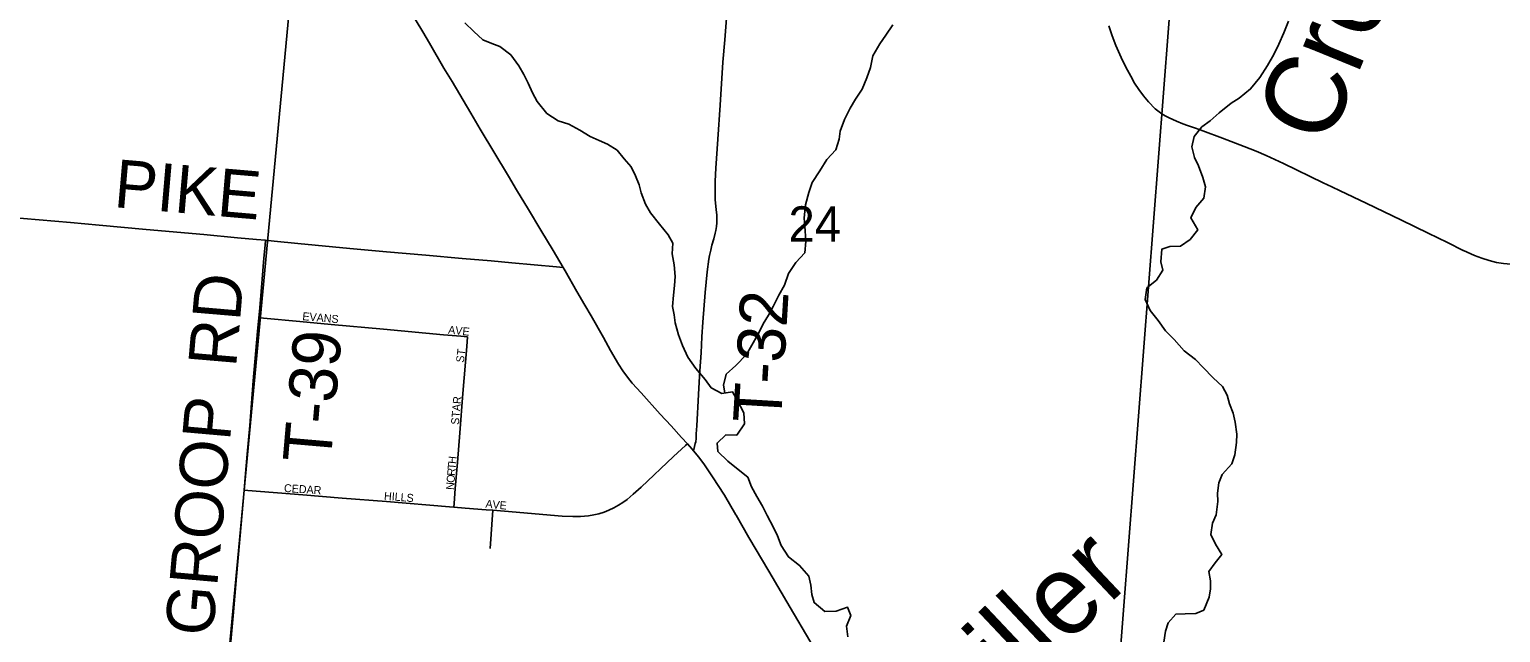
# Model space of a CAD drawing. Extents: x 1410790 to 1770854, y 566777 to 831614.
# Drawn here: x 1576682 to 1585877, y 711218 to 714986 of the extents above; entities that cross this region are included whole.
import ezdxf

# ---------------------------------------------------------------- set-up
doc = ezdxf.new("R2010")
doc.units = 0
for name, color, linetype in [('GM_X_County_Road', 7, 'Continuous'), ('GM_X_County_Road_Text', 7, 'Continuous'), ('GM_X_Minor_River', 7, 'Continuous'), ('GM_X_Minor_River_Text', 7, 'Continuous'), ('GM_X_Section', 7, 'Continuous'), ('GM_X_Section_Text', 7, 'Continuous'), ('GM_X_Township_Road', 7, 'Continuous'), ('GM_X_Township_Road_Text', 7, 'Continuous'), ('GM_X_Township_Subdivision', 7, 'Continuous'), ('GM_X_Township_Subdivision_Text', 7, 'Continuous')]:
    doc.layers.add(name, color=color, linetype=linetype)

msp = doc.modelspace()

# ---------------------------------------------------------------- linework, layer by layer
at = {"layer": 'GM_X_County_Road'}
for points in [[(1580017.1, 713499.7), (1579954.8, 713604.5), (1579879.1, 713731.2), (1579801.5, 713860.8), (1579727.2, 713984.1), (1579676.3, 714068.3), (1579499.3, 714363.7), (1579440.7, 714462.4), (1579323.6, 714659.7), (1579273.3, 714744.1), (1579181.7, 714899.4), (1579140.2, 714970.2), (1579064.6, 715096.8), (1578939.8, 715308.8), (1578831.3, 715492.4), (1578737.5, 715646.4), (1578678.6, 715744.8), (1578619.6, 715843.3), (1578494.3, 716054.8), (1578417.9, 716181.2), (1578356.6, 716278.4), (1578333.9, 716312.2)], [(1572937.4, 714145.1), (1573034.7, 714134.6), (1573198, 714119.1), (1573344.9, 714104.9), (1573590.1, 714084.2), (1573786.2, 714067.5), (1574021.8, 714044.2), (1574325.1, 714017.6), (1574717, 713980.8), (1574864, 713968.2), (1575043.7, 713951.7), (1575419.2, 713916), (1575685.6, 713891.3), (1576121.6, 713852), (1576334, 713832.7), (1576644.5, 713805.3), (1576938.5, 713779), (1577118.3, 713764.1), (1577412.2, 713736.7), (1577771.6, 713704.3), (1577983.2, 713684.6), (1578100.6, 713674)], [(1578100.6, 713674), (1578158.5, 713668.8)], [(1578158.5, 713668.8), (1578212.6, 713663.9), (1578359.1, 713649.3), (1578685.6, 713618.2), (1578914.3, 713597.5), (1579159.3, 713575.4), (1579387.9, 713555.3), (1579567.7, 713539.3), (1579698.3, 713528.2), (1579976, 713503.3), (1580017.1, 713499.7)], [(1580794.3, 712397.1), (1580758.6, 712437.8), (1580692.1, 712510.5), (1580625.1, 712582.4), (1580504.6, 712715), (1580449.6, 712775.8), (1580419.2, 712814.1), (1580390.9, 712853.9), (1580364.3, 712894.9), (1580314.5, 712980.6), (1580269.4, 713060.5), (1580192.1, 713196.7), (1580152.5, 713264.3), (1580103.4, 713349.4), (1580030.2, 713477.6), (1580017.1, 713499.7)], [(1580832.8, 712353), (1580823.6, 712363.8), (1580794.3, 712397.1)], [(1581099.1, 711950.7), (1581096.8, 711954.6), (1581025.4, 712076.1), (1580950.5, 712192.1), (1580901.3, 712266.2), (1580864.9, 712314.8), (1580832.8, 712353)], [(1581826.3, 710707.1), (1581777.2, 710792.2), (1581559.3, 711167.2), (1581435.7, 711374), (1581304.4, 711601.1), (1581179.1, 711812.8), (1581099.1, 711950.7)]]:
    msp.add_lwpolyline(points, dxfattribs=at)
at = {"layer": 'GM_X_Minor_River'}
for points in [[(1583772, 711158.6), (1583782.5, 711226.7), (1583798.9, 711278.7), (1583847.2, 711332.4), (1583905.2, 711336), (1583971.1, 711337.5), (1584021.2, 711359.2), (1584055.8, 711439.1), (1584064.2, 711491.1), (1584064.6, 711541.2), (1584053, 711599.4), (1584093.4, 711653.2), (1584133.7, 711705), (1584094.3, 711771.5), (1584064.8, 711831.8), (1584075.4, 711901.9), (1584099.7, 711953.8), (1584110.4, 712037.9), (1584106.8, 712090), (1584115.2, 712154), (1584137.6, 712206), (1584196.1, 712271.7), (1584216.5, 712327.6), (1584227, 712405.7), (1584227.5, 712457.8), (1584218, 712532), (1584204.5, 712588.2), (1584183, 712646.4), (1584167.4, 712700.7), (1584137.9, 712755), (1584080.4, 712809.5), (1584016.9, 712874.1), (1583969.4, 712924.5), (1583899.9, 712979.1), (1583836.5, 713049.7), (1583783, 713102.2), (1583735.6, 713166.6), (1583686.1, 713231.1), (1583654.7, 713299.4), (1583665.2, 713371.5), (1583725.5, 713419.1), (1583765.9, 713482.9), (1583752.4, 713535.1), (1583758.9, 713613.2), (1583809, 713630.8), (1583876.9, 713632.3), (1583937.2, 713673.9), (1583983.6, 713733.7), (1583940.2, 713808.1), (1583972.7, 713874), (1584023, 713931.7), (1584031.5, 714001.8), (1584016, 714060), (1583988.6, 714134.3), (1583963, 714186.5), (1583947.6, 714252.8), (1583962, 714316.7), (1584010.4, 714376.5), (1584060.6, 714414.1), (1584116.9, 714463.8), (1584193.3, 714525.3), (1584243.5, 714557), (1584313.8, 714614.6), (1584372.3, 714686.2), (1584420.8, 714760), (1584459.3, 714829.8), (1584491.7, 714893.6), (1584522.2, 714963.5), (1584550.7, 715037.4)], [(1581572.1, 711455.9), (1581566.8, 711514.1), (1581553.4, 711570.5), (1581496.1, 711637.4), (1581426.6, 711690.4), (1581381.4, 711763.1), (1581358.1, 711823.6), (1581332.6, 711874.1), (1581293.5, 711948.8), (1581264.1, 712007.3), (1581228.8, 712067.9), (1581195.4, 712128.5), (1581172.1, 712189), (1581112.6, 712237.8), (1581047, 712288.8), (1580985.6, 712349.7), (1580980.3, 712401.9), (1581035.1, 712453.4), (1581103.2, 712450.6), (1581152.2, 712522.3), (1581147.1, 712590.6), (1581106, 712669.3), (1581076.5, 712721.8), (1581010.2, 712712.6), (1580942.5, 712747.4), (1580905, 712800.1), (1580847.7, 712866.9), (1580796.4, 712937.8), (1580763.3, 713012.4), (1580738, 713078.9), (1580718.9, 713153.3), (1580711.5, 713203.6), (1580702.1, 713255.8), (1580707, 713326), (1580713.8, 713386.1), (1580718.5, 713442.2), (1580711.4, 713514.5), (1580700.2, 713584.8), (1580703.1, 713651), (1580673.6, 713703.5), (1580620.3, 713770.3), (1580563, 713841.2), (1580533.6, 713893.7), (1580506.4, 713964.2), (1580493, 714014.5), (1580469.6, 714070.9), (1580442.2, 714127.4), (1580398.7, 714178.1), (1580355.3, 714230.7), (1580295.6, 714269.5), (1580243.7, 714292.2), (1580185.9, 714316.9), (1580122.2, 714355.8), (1580052.5, 714394.7), (1579986.5, 714415.5), (1579916.9, 714460.5), (1579855.7, 714535.4), (1579826.2, 714589.9), (1579798.9, 714650.4), (1579771.5, 714704.9), (1579740.1, 714757.4), (1579690.8, 714826.1), (1579623.2, 714879.1), (1579571.3, 714897.7), (1579515.5, 714920.4), (1579459.9, 714973.2), (1579402.5, 715028)], [(1581029.1, 712715.2), (1581020.9, 712764.6), (1581037.8, 712832.6), (1581096.6, 712886.1), (1581163.7, 712955.5), (1581204.7, 713027.3), (1581243.7, 713095), (1581268.4, 713146.9), (1581301.1, 713200.7), (1581329.9, 713254.5), (1581364.9, 713326.3), (1581401.7, 713388.1), (1581426.7, 713462), (1581471.7, 713529.7), (1581528.6, 713591.2), (1581535.5, 713661.3), (1581530.3, 713727.6), (1581523.3, 713809.9), (1581532.4, 713890), (1581553.4, 713968), (1581574.2, 714029.9), (1581621.2, 714101.6), (1581666.2, 714173.3), (1581723.1, 714232.8), (1581742, 714300.8), (1581748.7, 714350.8), (1581775.6, 714422.7), (1581812.6, 714494.5), (1581845.4, 714550.2), (1581886.3, 714611.9), (1581915.3, 714683.8), (1581938.1, 714747.7), (1581953.1, 714821.8), (1581998.1, 714895.4), (1582034.9, 714949.1), (1582077.8, 715014.8)], [(1581797.4, 711192.3), (1581788.2, 711258.7), (1581815.1, 711324.6), (1581795.7, 711377), (1581723.2, 711351.7), (1581653, 711350.6), (1581587.5, 711405.5), (1581572.1, 711455.9)]]:
    msp.add_lwpolyline(points, dxfattribs=at)
at = {"layer": 'GM_X_Section'}
for points in [[(1573281.6, 716755.8), (1578419.1, 716300.4), (1577923.7, 711041.4), (1572586.3, 711496.1)], [(1578419.1, 716300.4), (1583863.1, 715803.7), (1583457.2, 710550.8), (1577923.7, 711041.4)], [(1589194.8, 715318.7), (1588736.5, 710042.5), (1583457.2, 710550.8), (1583863.1, 715803.7)]]:
    msp.add_lwpolyline(points, close=True, dxfattribs=at)
at = {"layer": 'GM_X_Township_Road'}
for points in [[(1580873, 712852.3), (1580879.9, 712966.4), (1580885.2, 713066), (1580890.7, 713157.4), (1580905, 713342.3), (1580911.3, 713407), (1580917.9, 713471.9), (1580927.8, 713550.6), (1580932.2, 713572.9), (1580940.2, 713607.5), (1580948.2, 713637.2), (1580960, 713678), (1580968.5, 713712.6), (1580972.3, 713729.9), (1580976, 713754), (1580978.6, 713776.9), (1580979.4, 713793.7), (1580978.5, 713826.9), (1580975.3, 713859.8), (1580968.8, 713923.9), (1580968.1, 713972.7), (1580968.3, 714038), (1580972.7, 714119.8), (1580985, 714299.9), (1580998.3, 714512.8), (1581016.9, 714781.4), (1581028.9, 714921.8), (1581065.1, 715412.6)], [(1583427.8, 715007.3), (1583448.7, 714945.4), (1583472.1, 714884.4), (1583505, 714809.5), (1583533.5, 714750.7), (1583564.8, 714693.4), (1583588.8, 714650.6), (1583615, 714609.6), (1583643.9, 714570.5), (1583675.6, 714533.4), (1583718.7, 714490.3), (1583742.1, 714470.4), (1583759.5, 714459.1), (1583781.2, 714446.1), (1583805.5, 714433.1), (1583851.5, 714413.1), (1583891.4, 714397.1), (1583919.9, 714386.6), (1583963.5, 714371.4), (1583999.8, 714358.3)], [(1583999.8, 714358.3), (1584016.4, 714352.3), (1584138.8, 714306.3), (1584273.3, 714254.2), (1584348.9, 714224.7), (1584411.4, 714198.7), (1584439.2, 714186.5), (1584519.9, 714149.2), (1584768.2, 714028.5), (1584822.3, 714002.1)], [(1584822.3, 714002.1), (1584873.2, 713977.3), (1585035.5, 713900.9), (1585257.7, 713794.1), (1585423.5, 713712.5), (1585545.1, 713654.4), (1585643.7, 713604.6)], [(1578116.4, 713183.7), (1578122.1, 713246.6), (1578137.8, 713425.9), (1578148.2, 713556.5), (1578155.6, 713637.9), (1578158.5, 713668.8)], [(1585643.7, 713604.6), (1585644.9, 713604.1), (1585712.9, 713574.4), (1585758.6, 713556.9), (1585805.1, 713541.6), (1585850.7, 713529.7), (1585894.1, 713522.8), (1585940.1, 713520.1), (1586019.9, 713517.5)], [(1578023.8, 712107.9), (1578030.3, 712186), (1578043.6, 712332.9), (1578059.5, 712512.3), (1578081.7, 712789.8), (1578108.8, 713099.8), (1578116.4, 713183.7)], [(1580832.8, 712353), (1580839.4, 712380.4), (1580843.8, 712398.3), (1580846.2, 712410.6), (1580848.7, 712430.5), (1580850, 712458.9), (1580852.9, 712509), (1580863.5, 712705.5), (1580871, 712819.3), (1580873, 712852.3)], [(1577928.6, 711023.7), (1577955.3, 711323.5), (1577977.5, 711568.1), (1578005.8, 711894.5), (1578023.8, 712107.9)]]:
    msp.add_lwpolyline(points, dxfattribs=at)
at = {"layer": 'GM_X_Township_Subdivision'}
for points in [[(1578116.4, 713183.7), (1578144.4, 713181.3), (1578373.1, 713161.6), (1578568.9, 713142.8), (1578895.3, 713112.8), (1579270.8, 713078.6), (1579379.3, 713068.9), (1579420.8, 713065.6)], [(1579334.9, 712001.9), (1579336.7, 712025.5), (1579343.5, 712117.8), (1579357, 712281.6), (1579371.7, 712466.2), (1579391.8, 712711), (1579416.6, 713004.8), (1579420.8, 713065.6)], [(1579578.3, 711982.1), (1579651.3, 711976), (1580011.6, 711946.1), (1580077.5, 711942.5), (1580127.2, 711943.3), (1580176.6, 711947.5), (1580209.4, 711952.8), (1580241.8, 711960.6), (1580273.3, 711970.9), (1580304.1, 711983.2), (1580334.1, 711997.3), (1580363.2, 712013.3), (1580391.2, 712031.1), (1580418, 712050.5), (1580456.3, 712082.1), (1580505, 712126.4), (1580708.1, 712317.6), (1580782.6, 712386.3), (1580794.3, 712397.1)], [(1578023.8, 712107.9), (1578046.7, 712106), (1578390.6, 712078.5), (1578636.2, 712058.3), (1578914.6, 712036.1), (1579307.5, 712004.2), (1579334.9, 712001.9)], [(1579334.9, 712001.9), (1579405.7, 711995.8), (1579536.8, 711985.6), (1579578.3, 711982.1)], [(1579561.2, 711743.2), (1579578.3, 711982.1)]]:
    msp.add_lwpolyline(points, dxfattribs=at)

# ---------------------------------------------------------------- texts
at = {"layer": 'GM_X_County_Road_Text'}
msp.add_text('PIKE', height=300, rotation=355.05673, dxfattribs=at).set_placement((1577204.5, 713876.5))
at = {"layer": 'GM_X_Minor_River_Text'}
for s, height, rotation, p in [('Creek', 500.07, 67.72918, (1584797.5, 714247.1)), ('Miller', 500.3, 43.35395, (1582428.3, 710448.1))]:
    msp.add_text(s, height=height, rotation=rotation, dxfattribs=at).set_placement(p)
at = {"layer": 'GM_X_Section_Text'}
msp.add_text('24', height=221, rotation=0.00001, dxfattribs=at).set_placement((1581426.2, 713659.9))
at = {"layer": 'GM_X_Township_Road_Text'}
for s, rotation, p in [('RD', 85.1131, (1577973.4, 712870.9)), ('T-32', 86.59788, (1581378.5, 712521.8)), ('T-39', 85.0756, (1578564.3, 712270.7)), ('GROOP', 84.96779, (1577828.1, 711190.1))]:
    msp.add_text(s, height=300, rotation=rotation, dxfattribs=at).set_placement(p)
at = {"layer": 'GM_X_Township_Subdivision_Text'}
for s, rotation, p in [('EVANS', 355.02841, (1578386.6, 713170.1)), ('AVE', 353.8867, (1579297.5, 713086.5)), ('ST', 82.86657, (1579397.2, 712902.3)), ('STAR', 85.02799, (1579366.4, 712514.7)), ('T', 85.12576, (1579345.5, 712235.2)), ('H', 85.13895, (1579348.5, 712270.3)), ('O', 85.18552, (1579338.5, 712151.9)), ('R', 85.13753, (1579342.2, 712195.7)), ('CEDAR', 356.34522, (1578272, 712096.5)), ('HILLS', 355.33124, (1578896.9, 712048.1)), ('N', 86.15103, (1579335.5, 712108.2)), ('A', 353.95668, (1579530.8, 711999.7)), ('V', 353.95668, (1579574.5, 711995)), ('E', 354.51672, (1579618.8, 711990.3))]:
    msp.add_text(s, height=50, rotation=rotation, dxfattribs=at).set_placement(p)

doc.saveas('drawing.dxf')
